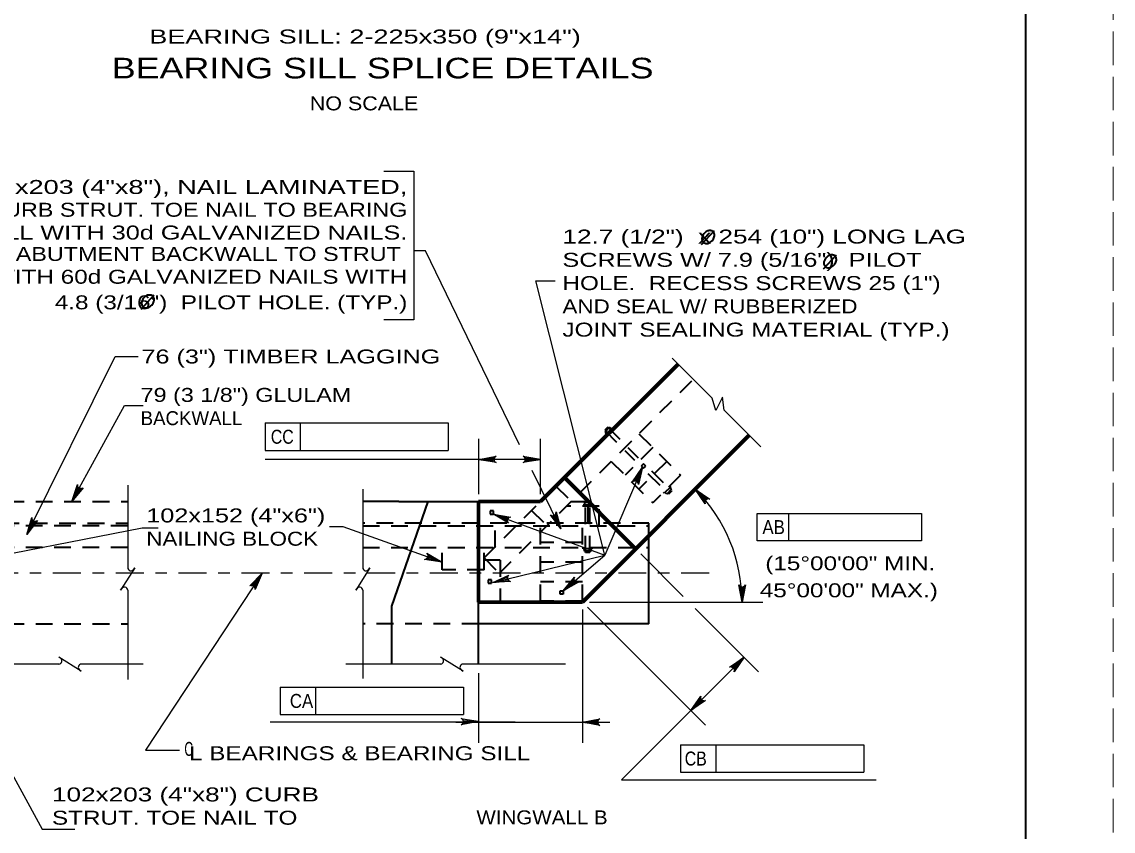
# Model space of a CAD drawing. Extents: x -6.4 to 73.1, y -66 to 0.
# Drawn here: x 58.62 to 68, y -35.45 to -28.5 of the extents above; entities that cross this region are included whole.
import ezdxf
from ezdxf.enums import TextEntityAlignment as Align

# ---------------------------------------------------------------- set-up
doc = ezdxf.new("R2010")
doc.units = 0
doc.header["$LTSCALE"] = 0.048
for name, pattern in [('DOT_DASHED', [7.7, 5, -1.2, 0.3, -1.2]), ('LONG_DASHED', [7.5, 6, -1.5]), ('MEDIUM_DASHED', [4.5, 3, -1.5])]:
    doc.linetypes.add(name, pattern=pattern)
for name, color, linetype, lineweight in [('1', 7, 'Continuous', 13), ('3', 7, 'Continuous', 35), ('4', 7, 'Continuous', 25), ('5', 7, 'Continuous', 25), ('52', 7, 'Continuous', 25), ('63', 7, 'LONG_DASHED', 13), ('8', 7, 'Continuous', 25)]:
    doc.layers.add(name, color=color, linetype=linetype, lineweight=lineweight)

msp = doc.modelspace()

# ---------------------------------------------------------------- hatches: boundary and pattern name
at = {"layer": '4'}
for points in [[(62.66542, -32.23733), (62.66542, -32.27675), (62.54733, -32.25708)], [(62.96075, -32.23733), (62.96075, -32.27675), (63.07883, -32.25708)], [(63.95383, -32.32417), (63.8985, -32.429), (63.91667, -32.43675)], [(64.47367, -32.61442), (64.50267, -32.58775), (64.40833, -32.51408)], [(62.67242, -32.728), (62.77983, -32.77808), (62.78658, -32.75958)], [(63.25325, -32.85558), (63.21, -32.74525), (63.19233, -32.75392)], [(60.68408, -33.23625), (60.61092, -33.3295), (60.62733, -33.34033)], [(63.27392, -33.388), (63.37, -33.31867), (63.35725, -33.30367)], [(64.825, -33.36592), (64.78567, -33.36758), (64.81042, -33.48475)], [(64.72983, -34.02833), (64.75767, -34.05617), (64.82725, -33.95875)], [(64.439, -34.31908), (64.46683, -34.347), (64.36942, -34.41658)], [(63.55575, -34.49658), (63.55575, -34.53592), (63.43767, -34.51625)]]:
    msp.add_hatch(color=256, dxfattribs=at).paths.add_polyline_path(points)

# ---------------------------------------------------------------- linework, layer by layer
at = {"layer": '1', "lineweight": 35}
msp.add_lwpolyline([(35.75, -43.25), (67.25, -43.25), (67.25, -22.75), (35.75, -22.75)], close=True, dxfattribs=at)
at = {"layer": '3', "lineweight": 25}
for p, q in [((64.20858, -31.38625), (64.553, -31.73058)), ((64.58625, -31.83617), (64.553, -31.73058)), ((64.6425, -31.72375), (64.58625, -31.83617)), ((64.6555, -31.83308), (64.6425, -31.72375)), ((64.6555, -31.83308), (64.97058, -32.14825))]:
    msp.add_line(p, q, dxfattribs=at)
at = {"layer": '3', "lineweight": 70}
for p, q in [((63.07883, -32.61867), (64.25992, -31.43758)), ((63.43767, -33.48475), (64.87242, -32.05)), ((63.283, -32.4145), (63.8955, -33.02692)), ((62.5455, -32.61867), (63.07883, -32.61867)), ((62.5455, -33.48475), (62.5455, -32.61867)), ((62.5455, -33.48475), (63.43767, -33.48475))]:
    msp.add_line(p, q, dxfattribs=at)
at = {"layer": '3', "linetype": 'MEDIUM_DASHED'}
for p, q in [((63.41458, -32.546), (64.3915, -31.56908)), ((63.67142, -31.98133), (63.63042, -32.02233)), ((63.6565, -31.98133), (63.63042, -32.00742)), ((63.6565, -31.98133), (63.91867, -32.2435)), ((63.67142, -31.98133), (63.68633, -31.99625)), ((63.63042, -32.00742), (63.88633, -32.26342)), ((63.63042, -32.02233), (63.64533, -32.03725)), ((63.69375, -31.98883), (63.63792, -32.04475)), ((63.63792, -32.04475), (63.64533, -32.05217)), ((63.69375, -31.98883), (63.70125, -31.99625)), ((63.92408, -32.0365), (64.28108, -32.3935)), ((64.04333, -32.15575), (63.80483, -32.39425)), ((63.68558, -32.275), (64.04258, -32.632)), ((64.16225, -32.27467), (63.92367, -32.51317)), ((64.03083, -32.35567), (64.20467, -32.5295)), ((64.00158, -32.37858), (64.17858, -32.55558)), ((64.28108, -32.3935), (64.04258, -32.632)), ((62.72433, -33.23625), (63.41458, -32.546)), ((63.21042, -32.48708), (63.34192, -32.61867)), ((64.16367, -32.55558), (64.14875, -32.54075)), ((64.20467, -32.51467), (64.16367, -32.55558)), ((64.20467, -32.5295), (64.17858, -32.55558)), ((64.19725, -32.49225), (64.18975, -32.48483)), ((64.20467, -32.51467), (64.18975, -32.49975)), ((62.59275, -33.10475), (63.07883, -32.61867)), ((63.45467, -32.62925), (63.45467, -32.65033)), ((63.51267, -32.62925), (63.45467, -32.62925)), ((63.50208, -32.61867), (63.46525, -32.61867)), ((63.46525, -33.05775), (63.46525, -32.61867)), ((63.50208, -33.05775), (63.50208, -32.61867)), ((63.51267, -32.62925), (63.51267, -32.65033)), ((63.00158, -32.696), (63.13308, -32.8275)), ((63.58208, -32.66083), (63.30492, -32.66083)), ((63.44417, -32.65033), (63.44417, -32.66083)), ((63.52317, -32.65033), (63.44417, -32.65033)), ((63.52317, -32.65033), (63.52317, -32.66083)), ((63.58208, -32.8295), (63.58208, -32.66083)), ((59.52958, -32.8275), (56.25708, -32.8275)), ((61.55017, -32.8275), (64.0085, -32.8275)), ((62.68917, -33.0135), (62.68917, -32.8275)), ((63.07675, -33.47708), (63.07675, -32.80467)), ((63.22117, -32.8295), (63.22117, -32.74467)), ((63.43767, -33.47708), (63.43767, -32.80467)), ((64.0085, -33.0135), (64.0085, -32.8275)), ((59.52958, -33.0135), (56.25708, -33.0135)), ((61.55017, -33.0135), (64.0085, -33.0135)), ((62.23192, -33.20592), (62.23192, -33.0135)), ((62.59283, -33.20592), (62.59283, -33.0135)), ((63.43767, -32.97275), (63.07675, -32.97275)), ((63.44417, -33.02608), (63.44417, -33.01558)), ((63.52317, -33.02608), (63.52317, -33.01558)), ((62.59275, -33.10475), (62.72433, -33.23625)), ((63.52317, -33.02608), (63.44417, -33.02608)), ((63.45467, -33.04717), (63.45467, -33.02608)), ((63.51267, -33.04717), (63.45467, -33.04717)), ((63.50208, -33.05775), (63.46525, -33.05775)), ((63.51267, -33.04717), (63.51267, -33.02608)), ((62.59283, -33.20592), (62.23192, -33.20592)), ((62.73158, -33.12383), (62.5455, -33.12383)), ((62.73158, -33.12383), (62.73158, -33.48475)), ((63.43767, -33.14092), (63.07675, -33.14092)), ((63.43767, -33.309), (63.07675, -33.309)), ((63.43767, -33.47708), (63.07675, -33.47708))]:
    msp.add_line(p, q, dxfattribs=at)
at = {"layer": '3', "linetype": 'MEDIUM_DASHED', "lineweight": 40}
for p, q in [((57.76425, -32.61867), (59.52958, -32.61867)), ((63.34192, -32.61867), (63.48717, -32.61867)), ((63.48717, -32.80467), (63.48717, -32.61867)), ((56.25708, -32.80467), (59.52958, -32.80467)), ((64.0085, -32.80467), (61.55017, -32.80467))]:
    msp.add_line(p, q, dxfattribs=at)
at = {"layer": '3', "lineweight": 40}
for p, q in [((61.85883, -32.61867), (61.55017, -32.61867)), ((61.85883, -32.61867), (62.5455, -32.61867)), ((64.0085, -33.67133), (64.0085, -32.80467)), ((64.0085, -33.67083), (62.5455, -33.67083))]:
    msp.add_line(p, q, dxfattribs=at)
at = {"layer": '3', "linetype": 'DOT_DASHED', "lineweight": 25}
msp.add_line((64.52733, -33.23625), (55.73008, -33.23625), dxfattribs=at)
at = {"layer": '3'}
msp.add_line((62.5455, -34.01658), (62.5455, -33.48475), dxfattribs=at)
at = {"layer": '3', "linetype": 'MEDIUM_DASHED'}
for points in [[(63.96367, -32.334), (63.98342, -32.31433), (63.96367, -32.29458), (63.94392, -32.31433)], [(62.6445, -32.728), (62.67242, -32.728), (62.67242, -32.70008), (62.6445, -32.70008)], [(62.62892, -33.32075), (62.65683, -33.32075), (62.65683, -33.29283), (62.62892, -33.29283)], [(63.27392, -33.41592), (63.246, -33.41592), (63.246, -33.388), (63.27392, -33.388)]]:
    msp.add_lwpolyline(points, close=True, dxfattribs=at)
msp.add_lwpolyline([(64.19725, -32.49225), (64.14133, -32.54817), (64.13383, -32.54075)], dxfattribs=at)
at = {"layer": '3'}
msp.add_lwpolyline([(61.80142, -34.01658), (61.80142, -33.52), (62.1115, -32.61867)], dxfattribs=at)
at = {"layer": '4'}
for p, q in [((61.72983, -29.77925), (61.98875, -29.77925)), ((58.66367, -32.90358), (59.42108, -31.37392)), ((59.42108, -31.37392), (59.61875, -31.37392)), ((60.71058, -31.9445), (62.28542, -31.9445)), ((60.71058, -31.9445), (60.71058, -32.18075)), ((61.01308, -31.9445), (61.01308, -32.18075)), ((62.28542, -31.9445), (62.28542, -32.18075)), ((62.54733, -32.55708), (62.54733, -32.07992)), ((63.07883, -32.55708), (63.07883, -32.07992)), ((60.71058, -32.18075), (62.28542, -32.18075)), ((63.07883, -32.25708), (60.71075, -32.25708)), ((63.25325, -32.85558), (63.00658, -32.35375)), ((62.67242, -32.728), (63.63167, -33.08167)), ((64.93917, -32.95892), (64.93917, -32.72267)), ((64.93917, -32.72267), (66.35117, -32.72267)), ((65.21292, -32.95892), (65.21292, -32.72267)), ((66.35117, -32.72267), (66.35117, -32.95892)), ((66.35117, -32.95892), (64.93917, -32.95892)), ((62.66833, -33.31425), (63.63167, -33.08167)), ((63.27392, -33.388), (63.63167, -33.08167)), ((63.93892, -33.07042), (64.30433, -33.43583)), ((57.7, -33.43217), (58.79408, -35.43508)), ((63.49917, -33.48475), (64.98758, -33.48475)), ((63.43767, -33.54633), (63.43767, -34.69342)), ((63.48117, -33.52825), (64.49467, -34.54183)), ((64.40708, -33.53867), (64.9525, -34.084)), ((64.82725, -33.95875), (64.36942, -34.41658)), ((62.5455, -34.0955), (62.5455, -34.69342)), ((60.84042, -34.21533), (62.41525, -34.21533)), ((60.84042, -34.21533), (60.84042, -34.45158)), ((61.14283, -34.21533), (61.14283, -34.45158)), ((62.41525, -34.21533), (62.41525, -34.45158)), ((64.36942, -34.41658), (63.774, -35.012)), ((62.86008, -34.51625), (60.75433, -34.51625)), ((60.84042, -34.45158), (62.41525, -34.45158)), ((62.34875, -34.51625), (63.43767, -34.51625)), ((63.43767, -34.51625), (63.67383, -34.51625)), ((64.28175, -34.71083), (65.8565, -34.71092)), ((64.58417, -34.71092), (64.58417, -34.94708)), ((65.8565, -34.71092), (65.8565, -34.94708)), ((63.774, -35.01208), (65.96158, -35.01208)), ((58.79408, -35.43508), (59.07658, -35.43508))]:
    msp.add_line(p, q, dxfattribs=at)
at = {"layer": '4', "linetype": 'MEDIUM_DASHED', "lineweight": 40}
for p, q in [((57.76425, -33.67083), (59.52958, -33.67083)), ((62.5455, -33.67083), (61.55017, -33.67083))]:
    msp.add_line(p, q, dxfattribs=at)
at = {"layer": '4'}
for points in [[(61.98875, -29.77925), (61.98875, -31.05725), (61.72983, -31.05725)], [(62.89717, -32.13125), (62.08817, -30.46608), (61.98875, -30.46608)], [(63.95383, -32.32417), (63.63167, -33.08167), (63.03742, -30.72333), (63.20458, -30.72333)], [(59.04975, -32.61867), (59.50192, -31.79558), (59.66183, -31.79558)], [(62.54733, -32.25708), (62.6965, -32.22908), (62.685, -32.23708), (62.67908, -32.24708), (62.67733, -32.25708), (62.67908, -32.26708), (62.685, -32.27708), (62.6965, -32.28508), (62.54733, -32.25708), (62.685, -32.27708), (62.67908, -32.26708), (62.54733, -32.25708), (62.67733, -32.25708), (62.67908, -32.24708), (62.54733, -32.25708), (62.685, -32.23708)], [(63.07883, -32.25708), (62.92967, -32.28508), (62.94117, -32.27708), (62.94708, -32.26708), (62.94883, -32.25708), (62.94708, -32.24708), (62.94117, -32.23708), (62.92967, -32.22908), (63.07883, -32.25708), (62.94117, -32.23708), (62.94708, -32.24708), (63.07883, -32.25708), (62.94883, -32.25708), (62.94708, -32.26708), (63.07883, -32.25708), (62.94117, -32.27708)], [(63.95383, -32.32417), (63.92117, -32.47233), (63.91833, -32.45867), (63.9115, -32.44925), (63.90292, -32.44383), (63.89308, -32.4415), (63.88158, -32.443), (63.86975, -32.4505), (63.95383, -32.32417), (63.88158, -32.443), (63.89308, -32.4415), (63.95383, -32.32417), (63.90292, -32.44383), (63.9115, -32.44925), (63.95383, -32.32417), (63.91833, -32.45867)], [(64.40833, -32.51408), (64.53358, -32.59975), (64.51983, -32.59725), (64.50858, -32.60017), (64.50025, -32.606), (64.49442, -32.61425), (64.4915, -32.6255), (64.494, -32.63933), (64.40833, -32.51408), (64.4915, -32.6255), (64.49442, -32.61425), (64.40833, -32.51408), (64.50025, -32.606), (64.50858, -32.60017), (64.40833, -32.51408), (64.51983, -32.59725)], [(62.67242, -32.728), (62.822, -32.75333), (62.8085, -32.75683), (62.7995, -32.76417), (62.79442, -32.773), (62.7925, -32.78292), (62.79467, -32.79442), (62.80267, -32.80583), (62.67242, -32.728), (62.79467, -32.79442), (62.7925, -32.78292), (62.67242, -32.728), (62.79442, -32.773), (62.7995, -32.76417), (62.67242, -32.728), (62.8085, -32.75683)], [(63.25325, -32.85558), (63.16233, -32.73408), (63.17458, -32.74092), (63.18617, -32.74175), (63.19592, -32.73892), (63.20408, -32.733), (63.2105, -32.72325), (63.21258, -32.70942), (63.25325, -32.85558), (63.2105, -32.72325), (63.20408, -32.733), (63.25325, -32.85558), (63.19592, -32.73892), (63.18617, -32.74175), (63.25325, -32.85558), (63.17458, -32.74092)], [(58.03733, -33.16225), (59.65425, -32.84517), (59.79167, -32.84517)], [(62.23192, -33.14058), (61.38258, -32.83592), (61.26317, -32.83592)], [(60.68408, -33.23625), (59.68208, -34.75767), (59.97525, -34.75767)], [(60.68408, -33.23625), (60.62542, -33.37617), (60.62508, -33.36217), (60.62, -33.35175), (60.61258, -33.34483), (60.60325, -33.34075), (60.59167, -33.34017), (60.57867, -33.34542), (60.68408, -33.23625), (60.59167, -33.34017), (60.60325, -33.34075), (60.68408, -33.23625), (60.61258, -33.34483), (60.62, -33.35175), (60.68408, -33.23625), (60.62508, -33.36217)], [(62.66833, -33.31425), (62.80675, -33.25208), (62.79742, -33.2625), (62.794, -33.27358), (62.79467, -33.28375), (62.79875, -33.29308), (62.80683, -33.30142), (62.81983, -33.30642), (62.66833, -33.31425), (62.80683, -33.30142), (62.79875, -33.29308), (62.66833, -33.31425), (62.79467, -33.28375), (62.794, -33.27358), (62.66833, -33.31425), (62.79742, -33.2625)], [(63.27392, -33.388), (63.369, -33.26975), (63.36542, -33.28325), (63.3675, -33.29475), (63.37267, -33.30342), (63.3805, -33.30992), (63.3915, -33.31367), (63.40542, -33.31225), (63.27392, -33.388), (63.3915, -33.31367), (63.3805, -33.30992), (63.27392, -33.388), (63.37267, -33.30342), (63.3675, -33.29475), (63.27392, -33.388), (63.36542, -33.28325)], [(64.81042, -33.48475), (64.7825, -33.33558), (64.79042, -33.34708), (64.80042, -33.353), (64.81042, -33.35475), (64.82042, -33.353), (64.83042, -33.34708), (64.83842, -33.33558), (64.81042, -33.48475), (64.83042, -33.34708), (64.82042, -33.353), (64.81042, -33.48475), (64.81042, -33.35475), (64.80042, -33.353), (64.81042, -33.48475), (64.79042, -33.34708)], [(64.82725, -33.95875), (64.74158, -34.084), (64.74408, -34.07025), (64.74117, -34.05892), (64.73533, -34.05067), (64.72708, -34.04483), (64.71575, -34.04192), (64.702, -34.04442), (64.82725, -33.95875), (64.71575, -34.04192), (64.72708, -34.04483), (64.82725, -33.95875), (64.73533, -34.05067), (64.74117, -34.05892), (64.82725, -33.95875), (64.74408, -34.07025)], [(64.36942, -34.41658), (64.45508, -34.29133), (64.45258, -34.30508), (64.4555, -34.31642), (64.46133, -34.32467), (64.46958, -34.3305), (64.48092, -34.33342), (64.49467, -34.33092), (64.36942, -34.41658), (64.48092, -34.33342), (64.46958, -34.3305), (64.36942, -34.41658), (64.46133, -34.32467), (64.4555, -34.31642), (64.36942, -34.41658), (64.45258, -34.30508)], [(62.5455, -34.51167), (62.39633, -34.53967), (62.40783, -34.53167), (62.41375, -34.52167), (62.4155, -34.51167), (62.41375, -34.50167), (62.40783, -34.49167), (62.39633, -34.48367), (62.5455, -34.51167), (62.40783, -34.49167), (62.41375, -34.50167), (62.5455, -34.51167), (62.4155, -34.51167), (62.41375, -34.52167), (62.5455, -34.51167), (62.40783, -34.53167)], [(63.43767, -34.51625), (63.58683, -34.48825), (63.57533, -34.49625), (63.56942, -34.50625), (63.56767, -34.51625), (63.56942, -34.52625), (63.57533, -34.53625), (63.58683, -34.54425), (63.43767, -34.51625), (63.57533, -34.53625), (63.56942, -34.52625), (63.43767, -34.51625), (63.56767, -34.51625), (63.56942, -34.50625), (63.43767, -34.51625), (63.57533, -34.49625)], [(64.28175, -34.71083), (64.28175, -34.94708), (65.8565, -34.94708)]]:
    msp.add_lwpolyline(points, dxfattribs=at)
for points in [[(62.66542, -32.23733), (62.66542, -32.27675), (62.54733, -32.25708)], [(62.96075, -32.23733), (62.96075, -32.27675), (63.07883, -32.25708)], [(63.95383, -32.32417), (63.8985, -32.429), (63.91667, -32.43675)], [(64.47367, -32.61442), (64.50267, -32.58775), (64.40833, -32.51408)], [(62.67242, -32.728), (62.77983, -32.77808), (62.78658, -32.75958)], [(63.25325, -32.85558), (63.21, -32.74525), (63.19233, -32.75392)], [(60.68408, -33.23625), (60.61092, -33.3295), (60.62733, -33.34033)], [(63.27392, -33.388), (63.37, -33.31867), (63.35725, -33.30367)], [(64.825, -33.36592), (64.78567, -33.36758), (64.81042, -33.48475)], [(64.72983, -34.02833), (64.75767, -34.05617), (64.82725, -33.95875)], [(64.439, -34.31908), (64.46683, -34.347), (64.36942, -34.41658)], [(63.55575, -34.49658), (63.55575, -34.53592), (63.43767, -34.51625)]]:
    msp.add_lwpolyline(points, close=True, dxfattribs=at)
msp.add_arc((63.43762, -33.48479), 1.37279, 0.00116, 44.99979, dxfattribs=at)
at = {"layer": '5', "lineweight": 35}
for p, q in [((64.46167, -30.41167), (64.57367, -30.28908)), ((65.50958, -30.62058), (65.62158, -30.498)), ((59.64533, -30.96558), (59.75733, -30.843))]:
    msp.add_line(p, q, dxfattribs=at)
for points in [[(64.562, -30.30117), (64.55325, -30.29433), (64.5445, -30.29192), (64.5335, -30.29092), (64.52725, -30.29092), (64.5165, -30.29342), (64.50667, -30.29792), (64.49975, -30.30183), (64.4865, -30.31242), (64.47617, -30.32592), (64.46992, -30.33858), (64.46625, -30.35017), (64.46517, -30.36092), (64.46625, -30.37017), (64.47075, -30.38333), (64.4755, -30.39017), (64.48517, -30.39742), (64.49967, -30.40092), (64.51617, -30.40042), (64.537, -30.39092), (64.55225, -30.37783), (64.56375, -30.36192), (64.57125, -30.34533), (64.57375, -30.32692), (64.5705, -30.31508), (64.5625, -30.30117)], [(65.60992, -30.51008), (65.60117, -30.50325), (65.59242, -30.50083), (65.58142, -30.49983), (65.57517, -30.49983), (65.56442, -30.50233), (65.55458, -30.50683), (65.54767, -30.51075), (65.53442, -30.52133), (65.52408, -30.53483), (65.51783, -30.5475), (65.51417, -30.55908), (65.51308, -30.56983), (65.51417, -30.57908), (65.51867, -30.59225), (65.52342, -30.59908), (65.53308, -30.60633), (65.54758, -30.60983), (65.56408, -30.60933), (65.58492, -30.59983), (65.60017, -30.58675), (65.61167, -30.57083), (65.61917, -30.55425), (65.62167, -30.53583), (65.61842, -30.524), (65.61042, -30.51008)], [(59.74567, -30.85508), (59.73692, -30.84825), (59.72817, -30.84583), (59.71717, -30.84483), (59.71092, -30.84483), (59.70017, -30.84733), (59.69033, -30.85183), (59.68342, -30.85575), (59.67017, -30.86633), (59.65983, -30.87983), (59.65358, -30.8925), (59.64992, -30.90408), (59.64883, -30.91483), (59.64992, -30.92408), (59.65442, -30.93725), (59.65917, -30.94408), (59.66883, -30.95133), (59.68333, -30.95483), (59.69983, -30.95433), (59.72067, -30.94483), (59.73592, -30.93175), (59.74742, -30.91583), (59.75492, -30.89925), (59.75742, -30.88083), (59.75417, -30.869), (59.74617, -30.85508)]]:
    msp.add_spline(points, degree=3, dxfattribs=at)
at = {"layer": '52'}
for points in [[(59.04975, -32.61867), (59.09708, -32.4745), (59.0985, -32.48842), (59.10442, -32.49842), (59.11233, -32.50475), (59.12192, -32.508), (59.13358, -32.50767), (59.14608, -32.50142), (59.04975, -32.61867), (59.13358, -32.50767), (59.12192, -32.508), (59.04975, -32.61867), (59.11233, -32.50475), (59.10442, -32.49842), (59.04975, -32.61867), (59.0985, -32.48842)], [(58.66367, -32.90358), (58.70475, -32.7575), (58.70683, -32.77133), (58.71317, -32.78108), (58.72133, -32.78708), (58.73108, -32.79), (58.74267, -32.78908), (58.75492, -32.78233), (58.66367, -32.90358), (58.74267, -32.78908), (58.73108, -32.79), (58.66367, -32.90358), (58.72133, -32.78708), (58.71317, -32.78108), (58.66367, -32.90358), (58.70683, -32.77133)], [(62.23192, -33.14058), (62.08208, -33.11658), (62.09558, -33.11292), (62.10458, -33.1055), (62.10958, -33.09667), (62.11133, -33.08667), (62.10908, -33.07525), (62.101, -33.06392), (62.23192, -33.14058), (62.10908, -33.07525), (62.11133, -33.08667), (62.23192, -33.14058), (62.10958, -33.09667), (62.10458, -33.1055), (62.23192, -33.14058), (62.09558, -33.11292)]]:
    msp.add_lwpolyline(points, dxfattribs=at)
at = {"layer": '63'}
msp.add_lwpolyline([(34, -44), (68, -44), (68, -22), (34, -22)], close=True, dxfattribs=at)
at = {"layer": '8'}
for p, q in [((59.52958, -32.48017), (59.52958, -33.18742)), ((61.55017, -32.51208), (61.55017, -33.18742)), ((59.52958, -33.38158), (59.52958, -34.14967)), ((61.55017, -33.38158), (61.55017, -34.14008)), ((58.93875, -34.01658), (57.67333, -34.01658)), ((59.66342, -34.01658), (59.133, -34.01658)), ((62.21975, -34.01658), (61.4055, -34.01658)), ((63.29375, -34.01658), (62.414, -34.01658))]:
    msp.add_line(p, q, dxfattribs=at)
for points in [[(59.58258, -33.20158), (59.59008, -33.18958), (59.46917, -33.382), (59.47725, -33.36917)], [(61.60317, -33.20158), (61.61058, -33.18958), (61.48967, -33.382), (61.49775, -33.36917)], [(59.11883, -34.06958), (59.13083, -34.07708), (58.93833, -33.95617), (58.95125, -33.96425)], [(62.39983, -34.06958), (62.41183, -34.07708), (62.21942, -33.95617), (62.23225, -33.96425)]]:
    msp.add_lwpolyline(points, dxfattribs=at)
for centre, start, end in [((59.558, -33.18739), 180, 330), ((61.57853, -33.18739), 180, 330), ((59.5013, -33.38427), 5.32859, 147.86724), ((61.52183, -33.38427), 5.32859, 147.86724), ((58.93612, -33.98832), 275.32859, 57.86724), ((59.13301, -34.04503), 90, 240), ((62.21714, -33.98832), 275.32859, 57.86724), ((62.41402, -34.04503), 90, 240)]:
    msp.add_arc(centre, 0.02841, start, end, dxfattribs=at)

# ---------------------------------------------------------------- texts
at = {"layer": '4'}
for s, height, width, p in [('BEARING SILL SPLICE DETAILS', 0.1772, 1.3, (61.72096, -28.98267)), ('CC', 0.12, 0.85, (60.85825, -32.12275)), ('AB', 0.12, 0.9, (65.08167, -32.89967)), ('CA', 0.12, 0.9, (61.02383, -34.39358))]:
    msp.add_text(s, height=height, dxfattribs=dict(at, width=width)).set_placement(p, align=Align.CENTER)
for s, width, p in [('NO SCALE', 1.15, (61.0945, -29.25733)), ('C', 0.65, (60.01667, -34.80625)), ('L BEARINGS & BEARING SILL', 1.3, (60.05667, -34.84333)), ('WINGWALL B', 1.1, (62.52708, -35.39442))]:
    msp.add_text(s, height=0.12, dxfattribs=dict(at, width=width)).set_placement(p)
at = {"layer": '4', "width": 0.85}
msp.add_text('CB', height=0.12, rotation=359.936, dxfattribs=at).set_placement((64.41218, -34.88886), align=Align.CENTER)
at = {"layer": '5'}
for s, width, p in [('BEARING SILL: 2-225x350 (9"x14")', 1.45, (61.56967, -28.68283)), ('(15°00\'00" MIN.', 1.3, (65.74054, -33.21075)), ('45°00\'00" MAX.)', 1.3, (65.72779, -33.44275))]:
    msp.add_text(s, height=0.12, dxfattribs=dict(at, width=width)).set_placement(p, align=Align.CENTER)
for s, width, p in [('4-102x203 (4"x8"), NAIL LAMINATED,', 1.45, (61.93325, -29.976)), ('CURB STRUT. TOE NAIL TO BEARING', 1.25, (61.93325, -30.17183)), ('SILL WITH 30d GALVANIZED NAILS.', 1.35, (61.93325, -30.36767)), ('NAIL ABUTMENT BACKWALL TO STRUT ', 1.25, (61.93325, -30.55183)), ('WITH 60d GALVANIZED NAILS WITH', 1.3, (61.93325, -30.74767)), ('4.8 (3/16")  PILOT HOLE. (TYP.)', 1.3, (61.93325, -30.96758))]:
    msp.add_text(s, height=0.12, dxfattribs=dict(at, width=width)).set_placement(p, align=Align.RIGHT)
for s, width, p in [('12.7 (1/2")  x 254 (10") LONG LAG', 1.4, (63.2665, -30.40217)), ('SCREWS W/ 7.9 (5/16")  PILOT', 1.35, (63.2665, -30.60217)), ('HOLE.  RECESS SCREWS 25 (1")', 1.3, (63.2665, -30.80217)), ('AND SEAL W/ RUBBERIZED', 1.2, (63.2665, -31.00217)), ('JOINT SEALING MATERIAL (TYP.)', 1.3, (63.2665, -31.20217)), ('76 (3") TIMBER LAGGING', 1.35, (59.64817, -31.43317)), ('79 (3 1/8") GLULAM', 1.25, (59.64083, -31.76325)), ('102x152 (4"x6")', 1.35, (59.68942, -32.79933)), ('NAILING BLOCK', 1.2, (59.68942, -32.99933)), ('102x203 (4"x8") CURB', 1.4, (58.87875, -35.1975)), ('STRUT. TOE NAIL TO', 1.3, (58.87875, -35.3975))]:
    msp.add_text(s, height=0.12, dxfattribs=dict(at, width=width)).set_placement(p)
msp.add_text('BACKWALL', height=0.12, dxfattribs=at).set_placement((59.64083, -31.96325))

doc.saveas('drawing.dxf')
